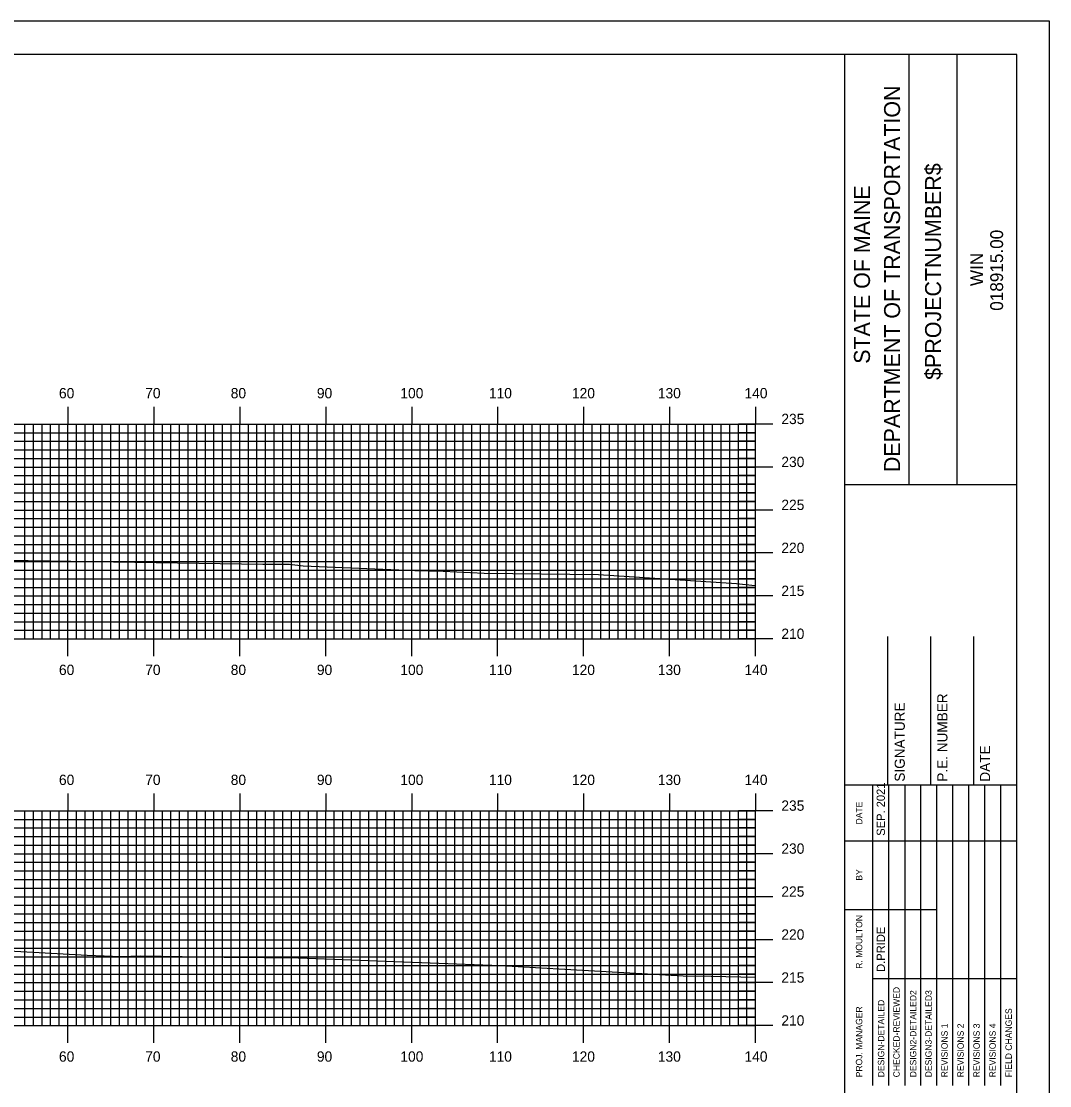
# Model space of a CAD drawing. Extents: x 1820031 to 1820374, y 442591 to 442811.
# Drawn here: x 1820251.3 to 1820370.9, y 442686.7 to 442810.5 of the extents above; entities that cross this region are included whole.
import ezdxf

# ---------------------------------------------------------------- set-up
doc = ezdxf.new("R2010")
doc.units = 0
for name, color, linetype in [('BORDER', 7, 'Continuous'), ('H_V ANNOTATION', 7, 'Continuous'), ('MAJOR', 7, 'Continuous'), ('MINOR', 7, 'Continuous'), ('PLOT BOUNDARY', 7, 'Continuous'), ('S_Roadway_Centerline', 7, 'Continuous')]:
    doc.layers.add(name, color=color, linetype=linetype)

msp = doc.modelspace()

# ---------------------------------------------------------------- linework, layer by layer
at = {"layer": 'BORDER'}
for p, q in [((1820347.09, 442596.67), (1820347.09, 442806.67)), ((1820354.55, 442756.66), (1820354.55, 442806.66)), ((1820360.14, 442756.66), (1820360.14, 442806.66)), ((1820347.09, 442756.65), (1820367.09, 442756.65)), ((1820352.09, 442721.67), (1820352.09, 442738.97)), ((1820357.09, 442721.67), (1820357.09, 442738.97)), ((1820362.09, 442721.67), (1820362.09, 442738.97)), ((1820347.09, 442721.67), (1820367.09, 442721.67))]:
    msp.add_line(p, q, dxfattribs=at)
msp.add_lwpolyline([(1820047.09, 442596.67), (1820367.09, 442596.67), (1820367.09, 442806.67), (1820047.09, 442806.67)], close=True, dxfattribs=at)
for points in [[(1820350.32, 442715.17), (1820350.32, 442721.67)], [(1820352.19, 442686.68), (1820352.19, 442721.67)], [(1820354.05, 442721.67), (1820354.05, 442686.68)], [(1820355.91, 442686.68), (1820355.91, 442721.67)], [(1820357.78, 442686.68), (1820357.78, 442721.67)], [(1820359.64, 442686.68), (1820359.64, 442721.67)], [(1820361.5, 442686.68), (1820361.5, 442721.67)], [(1820363.37, 442686.68), (1820363.37, 442721.67)], [(1820365.23, 442686.68), (1820365.23, 442721.67)], [(1820350.32, 442686.68), (1820350.32, 442720.26)], [(1820347.09, 442715.17), (1820367.09, 442715.17)], [(1820347.09, 442707.17), (1820350.32, 442707.17)], [(1820350.32, 442707.17), (1820357.77, 442707.17)], [(1820350.32, 442699.17), (1820367.09, 442699.17)]]:
    msp.add_lwpolyline(points, dxfattribs=at)
at = {"layer": 'MAJOR'}
for p, q in [((1820256.69, 442765.67), (1820256.69, 442763.67)), ((1820266.69, 442765.67), (1820266.69, 442763.67)), ((1820276.69, 442765.67), (1820276.69, 442763.67)), ((1820286.69, 442765.67), (1820286.69, 442763.67)), ((1820296.69, 442765.67), (1820296.69, 442763.67)), ((1820306.69, 442765.67), (1820306.69, 442763.67)), ((1820316.69, 442765.67), (1820316.69, 442763.67)), ((1820326.69, 442765.67), (1820326.69, 442763.67)), ((1820336.69, 442765.67), (1820336.69, 442763.67)), ((1820056.69, 442763.67), (1820336.69, 442763.67)), ((1820056.69, 442763.67), (1820336.69, 442763.67)), ((1820256.69, 442738.67), (1820256.69, 442763.67)), ((1820266.69, 442738.67), (1820266.69, 442763.67)), ((1820276.69, 442738.67), (1820276.69, 442763.67)), ((1820286.69, 442738.67), (1820286.69, 442763.67)), ((1820296.69, 442738.67), (1820296.69, 442763.67)), ((1820306.69, 442738.67), (1820306.69, 442763.67)), ((1820316.69, 442738.67), (1820316.69, 442763.67)), ((1820326.69, 442738.67), (1820326.69, 442763.67)), ((1820338.69, 442763.67), (1820334.69, 442763.67)), ((1820336.69, 442738.67), (1820336.69, 442763.67)), ((1820336.69, 442738.67), (1820336.69, 442763.67)), ((1820056.69, 442758.67), (1820336.69, 442758.67)), ((1820338.69, 442758.67), (1820334.69, 442758.67)), ((1820056.69, 442753.67), (1820336.69, 442753.67)), ((1820338.69, 442753.67), (1820334.69, 442753.67)), ((1820056.69, 442748.67), (1820336.69, 442748.67)), ((1820338.69, 442748.67), (1820334.69, 442748.67)), ((1820056.69, 442743.67), (1820336.69, 442743.67)), ((1820338.69, 442743.67), (1820334.69, 442743.67)), ((1820056.69, 442738.67), (1820336.69, 442738.67)), ((1820056.69, 442738.67), (1820336.69, 442738.67)), ((1820256.69, 442736.66), (1820256.69, 442738.67)), ((1820266.69, 442736.66), (1820266.69, 442738.67)), ((1820276.69, 442736.66), (1820276.69, 442738.67)), ((1820286.69, 442736.66), (1820286.69, 442738.67)), ((1820296.69, 442736.66), (1820296.69, 442738.67)), ((1820306.69, 442736.66), (1820306.69, 442738.67)), ((1820316.69, 442736.66), (1820316.69, 442738.67)), ((1820326.69, 442736.66), (1820326.69, 442738.67)), ((1820338.69, 442738.67), (1820334.69, 442738.67)), ((1820336.69, 442736.66), (1820336.69, 442738.67)), ((1820256.69, 442720.67), (1820256.69, 442718.67)), ((1820266.69, 442720.67), (1820266.69, 442718.67)), ((1820276.69, 442720.67), (1820276.69, 442718.67)), ((1820286.69, 442720.67), (1820286.69, 442718.67)), ((1820296.69, 442720.67), (1820296.69, 442718.67)), ((1820306.69, 442720.67), (1820306.69, 442718.67)), ((1820316.69, 442720.67), (1820316.69, 442718.67)), ((1820326.69, 442720.67), (1820326.69, 442718.67)), ((1820336.69, 442720.67), (1820336.69, 442718.67)), ((1820056.69, 442718.67), (1820336.69, 442718.67)), ((1820056.69, 442718.67), (1820336.69, 442718.67)), ((1820256.69, 442693.67), (1820256.69, 442718.67)), ((1820266.69, 442693.67), (1820266.69, 442718.67)), ((1820276.69, 442693.67), (1820276.69, 442718.67)), ((1820286.69, 442693.67), (1820286.69, 442718.67)), ((1820296.69, 442693.67), (1820296.69, 442718.67)), ((1820306.69, 442693.67), (1820306.69, 442718.67)), ((1820316.69, 442693.67), (1820316.69, 442718.67)), ((1820326.69, 442693.67), (1820326.69, 442718.67)), ((1820338.69, 442718.67), (1820334.69, 442718.67)), ((1820336.69, 442693.67), (1820336.69, 442718.67)), ((1820336.69, 442693.67), (1820336.69, 442718.67)), ((1820056.69, 442713.67), (1820336.69, 442713.67)), ((1820338.69, 442713.67), (1820334.69, 442713.67)), ((1820056.69, 442708.67), (1820336.69, 442708.67)), ((1820338.69, 442708.67), (1820334.69, 442708.67)), ((1820056.69, 442703.67), (1820336.69, 442703.67)), ((1820338.69, 442703.67), (1820334.69, 442703.67)), ((1820056.69, 442698.67), (1820336.69, 442698.67)), ((1820338.69, 442698.67), (1820334.69, 442698.67)), ((1820056.69, 442693.67), (1820336.69, 442693.67)), ((1820056.69, 442693.67), (1820336.69, 442693.67)), ((1820256.69, 442691.66), (1820256.69, 442693.67)), ((1820266.69, 442691.66), (1820266.69, 442693.67)), ((1820276.69, 442691.66), (1820276.69, 442693.67)), ((1820286.69, 442691.66), (1820286.69, 442693.67)), ((1820296.69, 442691.66), (1820296.69, 442693.67)), ((1820306.69, 442691.66), (1820306.69, 442693.67)), ((1820316.69, 442691.66), (1820316.69, 442693.67)), ((1820326.69, 442691.66), (1820326.69, 442693.67)), ((1820338.69, 442693.67), (1820334.69, 442693.67)), ((1820336.69, 442691.66), (1820336.69, 442693.67))]:
    msp.add_line(p, q, dxfattribs=at)
at = {"layer": 'MINOR'}
for p, q in [((1820251.69, 442738.67), (1820251.69, 442763.67)), ((1820252.69, 442738.67), (1820252.69, 442763.67)), ((1820253.69, 442738.67), (1820253.69, 442763.67)), ((1820254.69, 442738.67), (1820254.69, 442763.67)), ((1820255.69, 442738.67), (1820255.69, 442763.67)), ((1820257.69, 442738.67), (1820257.69, 442763.67)), ((1820258.69, 442738.67), (1820258.69, 442763.67)), ((1820259.69, 442738.67), (1820259.69, 442763.67)), ((1820260.69, 442738.67), (1820260.69, 442763.67)), ((1820261.69, 442738.67), (1820261.69, 442763.67)), ((1820262.69, 442738.67), (1820262.69, 442763.67)), ((1820263.69, 442738.67), (1820263.69, 442763.67)), ((1820264.69, 442738.67), (1820264.69, 442763.67)), ((1820265.69, 442738.67), (1820265.69, 442763.67)), ((1820267.69, 442738.67), (1820267.69, 442763.67)), ((1820268.69, 442738.67), (1820268.69, 442763.67)), ((1820269.69, 442738.67), (1820269.69, 442763.67)), ((1820270.69, 442738.67), (1820270.69, 442763.67)), ((1820271.69, 442738.67), (1820271.69, 442763.67)), ((1820272.69, 442738.67), (1820272.69, 442763.67)), ((1820273.69, 442738.67), (1820273.69, 442763.67)), ((1820274.69, 442738.67), (1820274.69, 442763.67)), ((1820275.69, 442738.67), (1820275.69, 442763.67)), ((1820277.69, 442738.67), (1820277.69, 442763.67)), ((1820278.69, 442738.67), (1820278.69, 442763.67)), ((1820279.69, 442738.67), (1820279.69, 442763.67)), ((1820280.69, 442738.67), (1820280.69, 442763.67)), ((1820281.69, 442738.67), (1820281.69, 442763.67)), ((1820282.69, 442738.67), (1820282.69, 442763.67)), ((1820283.69, 442738.67), (1820283.69, 442763.67)), ((1820284.69, 442738.67), (1820284.69, 442763.67)), ((1820285.69, 442738.67), (1820285.69, 442763.67)), ((1820287.69, 442738.67), (1820287.69, 442763.67)), ((1820288.69, 442738.67), (1820288.69, 442763.67)), ((1820289.69, 442738.67), (1820289.69, 442763.67)), ((1820290.69, 442738.67), (1820290.69, 442763.67)), ((1820291.69, 442738.67), (1820291.69, 442763.67)), ((1820292.69, 442738.67), (1820292.69, 442763.67)), ((1820293.69, 442738.67), (1820293.69, 442763.67)), ((1820294.69, 442738.67), (1820294.69, 442763.67)), ((1820295.69, 442738.67), (1820295.69, 442763.67)), ((1820297.69, 442738.67), (1820297.69, 442763.67)), ((1820298.69, 442738.67), (1820298.69, 442763.67)), ((1820299.69, 442738.67), (1820299.69, 442763.67)), ((1820300.69, 442738.67), (1820300.69, 442763.67)), ((1820301.69, 442738.67), (1820301.69, 442763.67)), ((1820302.69, 442738.67), (1820302.69, 442763.67)), ((1820303.69, 442738.67), (1820303.69, 442763.67)), ((1820304.69, 442738.67), (1820304.69, 442763.67)), ((1820305.69, 442738.67), (1820305.69, 442763.67)), ((1820307.69, 442738.67), (1820307.69, 442763.67)), ((1820308.69, 442738.67), (1820308.69, 442763.67)), ((1820309.69, 442738.67), (1820309.69, 442763.67)), ((1820310.69, 442738.67), (1820310.69, 442763.67)), ((1820311.69, 442738.67), (1820311.69, 442763.67)), ((1820312.69, 442738.67), (1820312.69, 442763.67)), ((1820313.69, 442738.67), (1820313.69, 442763.67)), ((1820314.69, 442738.67), (1820314.69, 442763.67)), ((1820315.69, 442738.67), (1820315.69, 442763.67)), ((1820317.69, 442738.67), (1820317.69, 442763.67)), ((1820318.69, 442738.67), (1820318.69, 442763.67)), ((1820319.69, 442738.67), (1820319.69, 442763.67)), ((1820320.69, 442738.67), (1820320.69, 442763.67)), ((1820321.69, 442738.67), (1820321.69, 442763.67)), ((1820322.69, 442738.67), (1820322.69, 442763.67)), ((1820323.69, 442738.67), (1820323.69, 442763.67)), ((1820324.69, 442738.67), (1820324.69, 442763.67)), ((1820325.69, 442738.67), (1820325.69, 442763.67)), ((1820327.69, 442738.67), (1820327.69, 442763.67)), ((1820328.69, 442738.67), (1820328.69, 442763.67)), ((1820329.69, 442738.67), (1820329.69, 442763.67)), ((1820330.69, 442738.67), (1820330.69, 442763.67)), ((1820331.69, 442738.67), (1820331.69, 442763.67)), ((1820332.69, 442738.67), (1820332.69, 442763.67)), ((1820333.69, 442738.67), (1820333.69, 442763.67)), ((1820334.69, 442738.67), (1820334.69, 442763.67)), ((1820335.69, 442738.67), (1820335.69, 442763.67)), ((1820056.69, 442762.67), (1820336.69, 442762.67)), ((1820336.69, 442762.67), (1820334.69, 442762.67)), ((1820056.69, 442761.67), (1820336.69, 442761.67)), ((1820336.69, 442761.67), (1820334.69, 442761.67)), ((1820056.69, 442760.67), (1820336.69, 442760.67)), ((1820336.69, 442760.67), (1820334.69, 442760.67)), ((1820056.69, 442759.67), (1820336.69, 442759.67)), ((1820336.69, 442759.67), (1820334.69, 442759.67)), ((1820056.69, 442757.67), (1820336.69, 442757.67)), ((1820336.69, 442757.67), (1820334.69, 442757.67)), ((1820056.69, 442756.67), (1820336.69, 442756.67)), ((1820336.69, 442756.67), (1820334.69, 442756.67)), ((1820056.69, 442755.67), (1820336.69, 442755.67)), ((1820336.69, 442755.67), (1820334.69, 442755.67)), ((1820056.69, 442754.67), (1820336.69, 442754.67)), ((1820336.69, 442754.67), (1820334.69, 442754.67)), ((1820056.69, 442752.67), (1820336.69, 442752.67)), ((1820336.69, 442752.67), (1820334.69, 442752.67)), ((1820056.69, 442751.67), (1820336.69, 442751.67)), ((1820336.69, 442751.67), (1820334.69, 442751.67)), ((1820056.69, 442750.67), (1820336.69, 442750.67)), ((1820336.69, 442750.67), (1820334.69, 442750.67)), ((1820056.69, 442749.67), (1820336.69, 442749.67)), ((1820336.69, 442749.67), (1820334.69, 442749.67)), ((1820056.69, 442747.67), (1820336.69, 442747.67)), ((1820336.69, 442747.67), (1820334.69, 442747.67)), ((1820056.69, 442746.67), (1820336.69, 442746.67)), ((1820336.69, 442746.67), (1820334.69, 442746.67)), ((1820056.69, 442745.67), (1820336.69, 442745.67)), ((1820336.69, 442745.67), (1820334.69, 442745.67)), ((1820056.69, 442744.67), (1820336.69, 442744.67)), ((1820336.69, 442744.67), (1820334.69, 442744.67)), ((1820056.69, 442742.67), (1820336.69, 442742.67)), ((1820336.69, 442742.67), (1820334.69, 442742.67)), ((1820056.69, 442741.67), (1820336.69, 442741.67)), ((1820336.69, 442741.67), (1820334.69, 442741.67)), ((1820056.69, 442740.67), (1820336.69, 442740.67)), ((1820336.69, 442740.67), (1820334.69, 442740.67)), ((1820056.69, 442739.67), (1820336.69, 442739.67)), ((1820336.69, 442739.67), (1820334.69, 442739.67)), ((1820251.69, 442693.67), (1820251.69, 442718.67)), ((1820252.69, 442693.67), (1820252.69, 442718.67)), ((1820253.69, 442693.67), (1820253.69, 442718.67)), ((1820254.69, 442693.67), (1820254.69, 442718.67)), ((1820255.69, 442693.67), (1820255.69, 442718.67)), ((1820257.69, 442693.67), (1820257.69, 442718.67)), ((1820258.69, 442693.67), (1820258.69, 442718.67)), ((1820259.69, 442693.67), (1820259.69, 442718.67)), ((1820260.69, 442693.67), (1820260.69, 442718.67)), ((1820261.69, 442693.67), (1820261.69, 442718.67)), ((1820262.69, 442693.67), (1820262.69, 442718.67)), ((1820263.69, 442693.67), (1820263.69, 442718.67)), ((1820264.69, 442693.67), (1820264.69, 442718.67)), ((1820265.69, 442693.67), (1820265.69, 442718.67)), ((1820267.69, 442693.67), (1820267.69, 442718.67)), ((1820268.69, 442693.67), (1820268.69, 442718.67)), ((1820269.69, 442693.67), (1820269.69, 442718.67)), ((1820270.69, 442693.67), (1820270.69, 442718.67)), ((1820271.69, 442693.67), (1820271.69, 442718.67)), ((1820272.69, 442693.67), (1820272.69, 442718.67)), ((1820273.69, 442693.67), (1820273.69, 442718.67)), ((1820274.69, 442693.67), (1820274.69, 442718.67)), ((1820275.69, 442693.67), (1820275.69, 442718.67)), ((1820277.69, 442693.67), (1820277.69, 442718.67)), ((1820278.69, 442693.67), (1820278.69, 442718.67)), ((1820279.69, 442693.67), (1820279.69, 442718.67)), ((1820280.69, 442693.67), (1820280.69, 442718.67)), ((1820281.69, 442693.67), (1820281.69, 442718.67)), ((1820282.69, 442693.67), (1820282.69, 442718.67)), ((1820283.69, 442693.67), (1820283.69, 442718.67)), ((1820284.69, 442693.67), (1820284.69, 442718.67)), ((1820285.69, 442693.67), (1820285.69, 442718.67)), ((1820287.69, 442693.67), (1820287.69, 442718.67)), ((1820288.69, 442693.67), (1820288.69, 442718.67)), ((1820289.69, 442693.67), (1820289.69, 442718.67)), ((1820290.69, 442693.67), (1820290.69, 442718.67)), ((1820291.69, 442693.67), (1820291.69, 442718.67)), ((1820292.69, 442693.67), (1820292.69, 442718.67)), ((1820293.69, 442693.67), (1820293.69, 442718.67)), ((1820294.69, 442693.67), (1820294.69, 442718.67)), ((1820295.69, 442693.67), (1820295.69, 442718.67)), ((1820297.69, 442693.67), (1820297.69, 442718.67)), ((1820298.69, 442693.67), (1820298.69, 442718.67)), ((1820299.69, 442693.67), (1820299.69, 442718.67)), ((1820300.69, 442693.67), (1820300.69, 442718.67)), ((1820301.69, 442693.67), (1820301.69, 442718.67)), ((1820302.69, 442693.67), (1820302.69, 442718.67)), ((1820303.69, 442693.67), (1820303.69, 442718.67)), ((1820304.69, 442693.67), (1820304.69, 442718.67)), ((1820305.69, 442693.67), (1820305.69, 442718.67)), ((1820307.69, 442693.67), (1820307.69, 442718.67)), ((1820308.69, 442693.67), (1820308.69, 442718.67)), ((1820309.69, 442693.67), (1820309.69, 442718.67)), ((1820310.69, 442693.67), (1820310.69, 442718.67)), ((1820311.69, 442693.67), (1820311.69, 442718.67)), ((1820312.69, 442693.67), (1820312.69, 442718.67)), ((1820313.69, 442693.67), (1820313.69, 442718.67)), ((1820314.69, 442693.67), (1820314.69, 442718.67)), ((1820315.69, 442693.67), (1820315.69, 442718.67)), ((1820317.69, 442693.67), (1820317.69, 442718.67)), ((1820318.69, 442693.67), (1820318.69, 442718.67)), ((1820319.69, 442693.67), (1820319.69, 442718.67)), ((1820320.69, 442693.67), (1820320.69, 442718.67)), ((1820321.69, 442693.67), (1820321.69, 442718.67)), ((1820322.69, 442693.67), (1820322.69, 442718.67)), ((1820323.69, 442693.67), (1820323.69, 442718.67)), ((1820324.69, 442693.67), (1820324.69, 442718.67)), ((1820325.69, 442693.67), (1820325.69, 442718.67)), ((1820327.69, 442693.67), (1820327.69, 442718.67)), ((1820328.69, 442693.67), (1820328.69, 442718.67)), ((1820329.69, 442693.67), (1820329.69, 442718.67)), ((1820330.69, 442693.67), (1820330.69, 442718.67)), ((1820331.69, 442693.67), (1820331.69, 442718.67)), ((1820332.69, 442693.67), (1820332.69, 442718.67)), ((1820333.69, 442693.67), (1820333.69, 442718.67)), ((1820334.69, 442693.67), (1820334.69, 442718.67)), ((1820335.69, 442693.67), (1820335.69, 442718.67)), ((1820056.69, 442717.67), (1820336.69, 442717.67)), ((1820056.69, 442716.67), (1820336.69, 442716.67)), ((1820336.69, 442717.67), (1820334.69, 442717.67)), ((1820336.69, 442716.67), (1820334.69, 442716.67)), ((1820056.69, 442715.67), (1820336.69, 442715.67)), ((1820336.69, 442715.67), (1820334.69, 442715.67)), ((1820056.69, 442714.67), (1820336.69, 442714.67)), ((1820336.69, 442714.67), (1820334.69, 442714.67)), ((1820056.69, 442712.67), (1820336.69, 442712.67)), ((1820056.69, 442711.67), (1820336.69, 442711.67)), ((1820336.69, 442712.67), (1820334.69, 442712.67)), ((1820336.69, 442711.67), (1820334.69, 442711.67)), ((1820056.69, 442710.67), (1820336.69, 442710.67)), ((1820336.69, 442710.67), (1820334.69, 442710.67)), ((1820056.69, 442709.67), (1820336.69, 442709.67)), ((1820336.69, 442709.67), (1820334.69, 442709.67)), ((1820056.69, 442707.67), (1820336.69, 442707.67)), ((1820056.69, 442706.67), (1820336.69, 442706.67)), ((1820336.69, 442707.67), (1820334.69, 442707.67)), ((1820336.69, 442706.67), (1820334.69, 442706.67)), ((1820056.69, 442705.67), (1820336.69, 442705.67)), ((1820336.69, 442705.67), (1820334.69, 442705.67)), ((1820056.69, 442704.67), (1820336.69, 442704.67)), ((1820336.69, 442704.67), (1820334.69, 442704.67)), ((1820056.69, 442702.67), (1820336.69, 442702.67)), ((1820056.69, 442701.67), (1820336.69, 442701.67)), ((1820336.69, 442702.67), (1820334.69, 442702.67)), ((1820336.69, 442701.67), (1820334.69, 442701.67)), ((1820056.69, 442700.67), (1820336.69, 442700.67)), ((1820336.69, 442700.67), (1820334.69, 442700.67)), ((1820056.69, 442699.67), (1820336.69, 442699.67)), ((1820336.69, 442699.67), (1820334.69, 442699.67)), ((1820056.69, 442697.67), (1820336.69, 442697.67)), ((1820056.69, 442696.67), (1820336.69, 442696.67)), ((1820336.69, 442697.67), (1820334.69, 442697.67)), ((1820336.69, 442696.67), (1820334.69, 442696.67)), ((1820056.69, 442695.67), (1820336.69, 442695.67)), ((1820336.69, 442695.67), (1820334.69, 442695.67)), ((1820056.69, 442694.67), (1820336.69, 442694.67)), ((1820336.69, 442694.67), (1820334.69, 442694.67))]:
    msp.add_line(p, q, dxfattribs=at)
at = {"layer": 'PLOT BOUNDARY'}
msp.add_lwpolyline([(1820030.9, 442590.55), (1820370.9, 442590.55), (1820370.9, 442810.55), (1820030.9, 442810.55)], close=True, dxfattribs=at)
at = {"layer": 'S_Roadway_Centerline'}
for points in [[(1820249.59, 442747.83), (1820279.36, 442747.36), (1820282.46, 442747.38), (1820284.08, 442747.19), (1820297.07, 442746.62), (1820300.35, 442746.56), (1820305.11, 442746.32), (1820318.4, 442746.16), (1820334.46, 442745.11), (1820336.6, 442744.87), (1820336.69, 442744.87)], [(1820245.62, 442702.62), (1820258.95, 442701.86), (1820262.88, 442701.7), (1820265.11, 442701.77), (1820274.88, 442701.63), (1820279.53, 442701.61), (1820280.69, 442701.61), (1820282.47, 442701.59), (1820307.03, 442700.66), (1820313.81, 442700.26), (1820328.27, 442699.46), (1820331.53, 442699.41), (1820336.69, 442699.31)]]:
    msp.add_lwpolyline(points, dxfattribs=at)

# ---------------------------------------------------------------- texts
at = {"layer": 'BORDER'}
for s, height, p in [('DEPARTMENT OF TRANSPORTATION', 1.8635, (1820353.5, 442758.08)), ('$PROJECTNUMBER$', 1.8635, (1820358.27, 442768.82)), ('STATE OF MAINE', 1.8635, (1820350, 442770.69)), ('018915.00', 1.491, (1820365.48, 442776.86)), ('WIN', 1.491, (1820363.16, 442779.73)), ('P.E. NUMBER', 1.1811, (1820359.01, 442722.06)), ('SIGNATURE', 1.181, (1820354.05, 442722.06)), ('DATE', 1.181, (1820363.97, 442722.06)), ('SEP. 2021', 0.969, (1820351.74, 442715.76)), ('DATE', 0.743, (1820349.1, 442717.08)), ('BY', 0.743, (1820349.1, 442710.54)), ('R. MOULTON', 0.745, (1820349.1, 442700.28)), ('D.PRIDE', 0.969, (1820351.74, 442699.92)), ('CHECKED-REVIEWED', 0.7455, (1820353.45, 442687.65)), ('DESIGN2-DETAILED2', 0.7455, (1820355.39, 442687.65)), ('DESIGN3-DETAILED3', 0.7455, (1820357.18, 442687.65)), ('PROJ. MANAGER', 0.7455, (1820349.1, 442687.65)), ('DESIGN-DETAILED', 0.7455, (1820351.66, 442687.65)), ('FIELD CHANGES', 0.7455, (1820366.5, 442687.65)), ('REVISIONS 1', 0.7455, (1820359.04, 442687.65)), ('REVISIONS 2', 0.7455, (1820360.91, 442687.65)), ('REVISIONS 3', 0.7455, (1820362.77, 442687.65)), ('REVISIONS 4', 0.7455, (1820364.63, 442687.65))]:
    msp.add_text(s, height=height, rotation=90, dxfattribs=at).set_placement(p)
at = {"layer": 'H_V ANNOTATION'}
for s, p in [('60', (1820255.66, 442766.67)), ('70', (1820265.69, 442766.67)), ('80', (1820275.64, 442766.67)), ('90', (1820285.66, 442766.67)), ('100', (1820295.37, 442766.67)), ('110', (1820305.67, 442766.67)), ('120', (1820315.33, 442766.67)), ('130', (1820325.32, 442766.67)), ('140', (1820335.4, 442766.67)), ('235', (1820339.69, 442763.67)), ('230', (1820339.69, 442758.67)), ('225', (1820339.69, 442753.67)), ('220', (1820339.69, 442748.67)), ('215', (1820339.69, 442743.67)), ('210', (1820339.69, 442738.67)), ('60', (1820255.66, 442734.47)), ('70', (1820265.69, 442734.47)), ('80', (1820275.64, 442734.47)), ('90', (1820285.66, 442734.47)), ('100', (1820295.37, 442734.47)), ('110', (1820305.67, 442734.47)), ('120', (1820315.33, 442734.47)), ('130', (1820325.32, 442734.47)), ('140', (1820335.4, 442734.47)), ('60', (1820255.66, 442721.67)), ('70', (1820265.69, 442721.67)), ('80', (1820275.64, 442721.67)), ('90', (1820285.66, 442721.67)), ('100', (1820295.37, 442721.67)), ('110', (1820305.67, 442721.67)), ('120', (1820315.33, 442721.67)), ('130', (1820325.32, 442721.67)), ('140', (1820335.4, 442721.67)), ('235', (1820339.69, 442718.67)), ('230', (1820339.69, 442713.67)), ('225', (1820339.69, 442708.67)), ('220', (1820339.69, 442703.67)), ('215', (1820339.69, 442698.67)), ('210', (1820339.69, 442693.67)), ('60', (1820255.66, 442689.47)), ('70', (1820265.69, 442689.47)), ('80', (1820275.64, 442689.47)), ('90', (1820285.66, 442689.47)), ('100', (1820295.37, 442689.47)), ('110', (1820305.67, 442689.47)), ('120', (1820315.33, 442689.47)), ('130', (1820325.32, 442689.47)), ('140', (1820335.4, 442689.47))]:
    msp.add_text(s, height=1.2, dxfattribs=at).set_placement(p)

doc.saveas('drawing.dxf')
